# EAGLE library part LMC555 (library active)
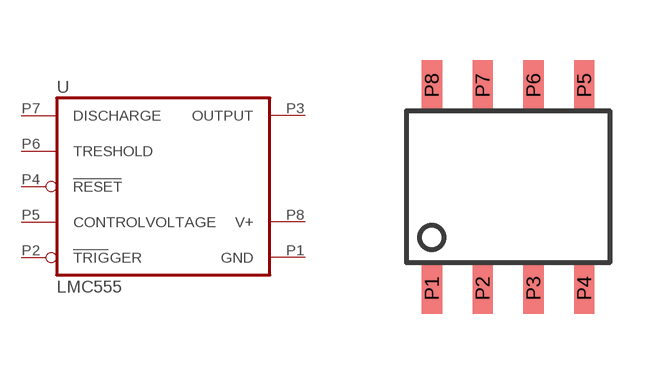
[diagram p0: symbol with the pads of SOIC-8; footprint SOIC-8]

Designator prefix U

## LMC555  [SOIC-8]
P1  GND  pwr
P2  TRIGGER
P3  OUTPUT  out
P4  RESET  in
P5  CONTROLVOLTAGE  pas
P6  TRESHOLD  in
P7  DISCHARGE  in
P8  V+  pwr

## Footprint SOIC-8 (pad centres in mm)
smd 0.508 x 1.27: P1 -1.905,-2.54; P2 -0.635,-2.54; P3 0.635,-2.54; P4 1.905,-2.54; P5 1.905,2.54; P6 0.635,2.54; P7 -0.635,2.54; P8 -1.905,2.54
